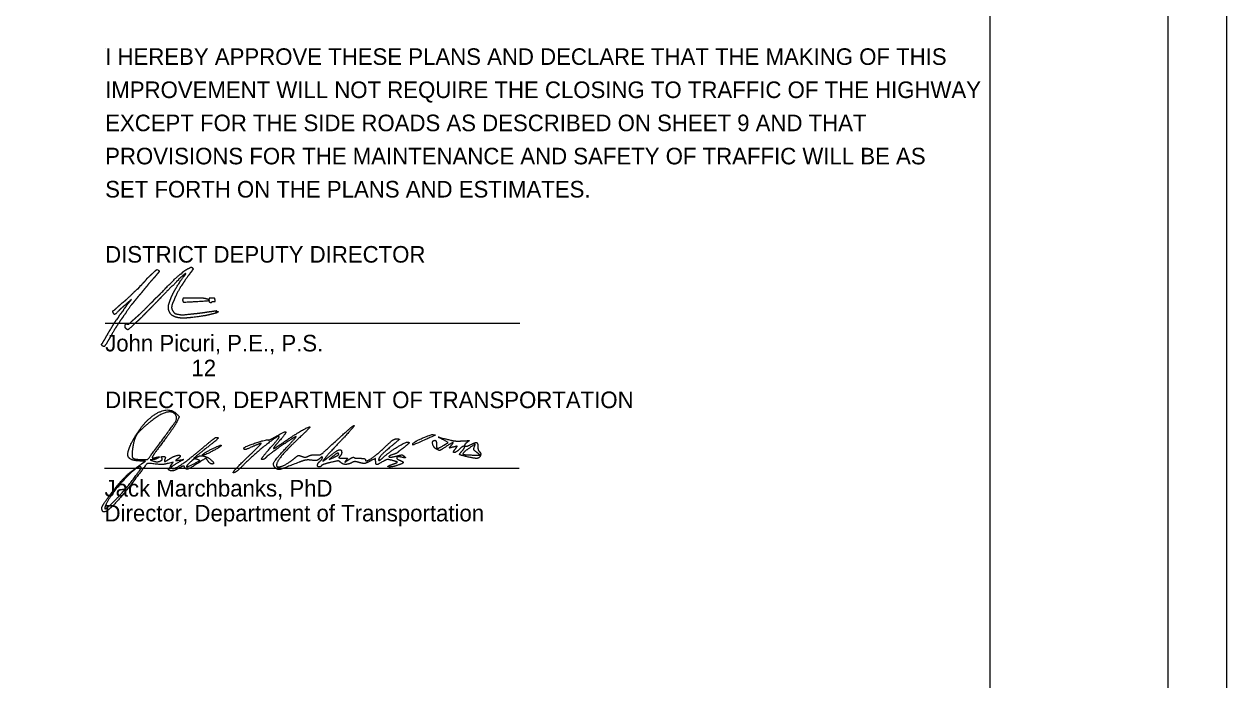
# Model space of a CAD drawing. Extents: x -5.4 to 71.3, y -12 to 22.
# Drawn here: x 23.84 to 34, y 5.54 to 11.08 of the extents above; entities that cross this region are included whole.
import ezdxf

# ---------------------------------------------------------------- set-up
doc = ezdxf.new("R2010")
doc.units = 0
for name, color, linetype in [('SH_Border', 7, 'Continuous'), ('SH_Cut_Line', 7, 'Continuous'), ('SH_Data', 7, 'Continuous'), ('SH_Text', 7, 'Continuous')]:
    doc.layers.add(name, color=color, linetype=linetype)

msp = doc.modelspace()

# ---------------------------------------------------------------- linework, layer by layer
at = {"layer": 'SH_Border'}
msp.add_line((32, 0.5), (32, 21.5), dxfattribs=at)
msp.add_lwpolyline([(1.5, 21.5), (33.5, 21.5), (33.5, 0.5), (1.5, 0.5)], close=True, dxfattribs=at)
at = {"layer": 'SH_Cut_Line'}
msp.add_lwpolyline([(0, 0), (34, 0), (34, 22), (0, 22)], close=True, dxfattribs=at)
at = {"layer": 'SH_Data'}
for p, q in [((24.528, 10.875), (24.528, 10.875)), ((24.528, 8.555), (28.028, 8.555)), ((24.523, 7.329), (28.023, 7.329))]:
    msp.add_line(p, q, dxfattribs=at)
at = {"layer": 'SH_Text'}
for p, q in [((25.184, 8.741), (25.184, 8.741)), ((25.407, 8.734), (25.407, 8.734)), ((24.703, 8.509), (24.703, 8.509)), ((24.512, 8.357), (24.512, 8.357)), ((24.986, 7.534), (24.986, 7.534)), ((27.125, 7.533), (27.125, 7.533)), ((25.351, 7.444), (25.351, 7.444)), ((25.723, 7.415), (25.723, 7.415)), ((26.5, 7.446), (26.5, 7.446)), ((27.577, 7.427), (27.577, 7.427)), ((25.306, 7.402), (25.306, 7.402))]:
    msp.add_line(p, q, dxfattribs=at)
for points in [[(24.953, 8.998), (24.964, 9.008), (24.973, 9.003)], [(24.747, 8.75), (24.75, 8.757), (24.744, 8.75)], [(25.277, 8.765), (25.186, 8.765), (25.184, 8.757)], [(25.429, 8.766), (25.407, 8.766), (25.404, 8.752)], [(25.442, 8.736), (25.457, 8.736), (25.456, 8.749)], [(27.389, 7.523), (27.425, 7.545), (27.384, 7.568)], [(26.448, 7.426), (26.419, 7.401), (26.459, 7.42)], [(27.637, 7.44), (27.694, 7.44), (27.665, 7.462)], [(24.838, 7.367), (24.869, 7.388), (24.831, 7.389)], [(25.081, 7.347), (25.102, 7.379), (25.06, 7.369)]]:
    msp.add_lwpolyline(points, dxfattribs=at)
for points in [[(24.88, 8.928), (24.88, 8.929), (24.894, 8.943), (24.911, 8.958)], [(24.911, 8.958), (24.928, 8.974), (24.947, 8.992), (24.953, 8.998)], [(24.956, 8.955), (24.949, 8.946), (24.941, 8.937), (24.938, 8.934)], [(24.976, 8.979), (24.972, 8.975), (24.963, 8.964), (24.956, 8.955)], [(24.973, 9.003), (24.985, 8.996), (24.985, 8.99), (24.976, 8.979)], [(24.999, 8.807), (25.069, 8.881), (25.161, 8.969), (25.17, 8.971)], [(25.119, 8.836), (25.131, 8.858), (25.186, 8.943), (25.193, 8.949)], [(25.21, 8.974), (25.21, 8.976), (25.185, 8.957), (25.162, 8.936)], [(25.17, 8.971), (25.174, 8.972), (25.178, 8.975), (25.178, 8.977)], [(25.178, 8.977), (25.178, 8.982), (25.204, 9.001), (25.23, 9.015)], [(25.193, 8.949), (25.197, 8.953), (25.21, 8.971), (25.21, 8.974)], [(25.238, 8.964), (25.23, 8.955), (25.227, 8.951), (25.2, 8.912)], [(25.23, 9.015), (25.253, 9.027), (25.258, 9.028), (25.268, 9.016)], [(25.242, 8.972), (25.242, 8.97), (25.24, 8.967), (25.238, 8.964)], [(25.252, 8.984), (25.246, 8.979), (25.242, 8.973), (25.242, 8.972)], [(25.261, 8.997), (25.261, 8.996), (25.257, 8.99), (25.252, 8.984)], [(25.267, 9.005), (25.264, 9.002), (25.261, 8.998), (25.261, 8.997)], [(25.268, 9.016), (25.271, 9.012), (25.271, 9.01), (25.267, 9.005)], [(24.771, 8.815), (24.787, 8.831), (24.804, 8.845), (24.807, 8.846)], [(24.807, 8.846), (24.811, 8.847), (24.813, 8.849), (24.812, 8.85)], [(24.812, 8.85), (24.811, 8.851), (24.814, 8.855), (24.818, 8.859)], [(24.818, 8.859), (24.822, 8.863), (24.825, 8.867), (24.824, 8.868)], [(24.824, 8.868), (24.823, 8.869), (24.825, 8.871), (24.829, 8.872)], [(24.829, 8.872), (24.833, 8.873), (24.836, 8.875), (24.836, 8.876)], [(24.836, 8.876), (24.836, 8.878), (24.846, 8.889), (24.858, 8.902)], [(24.863, 8.846), (24.857, 8.839), (24.846, 8.825), (24.837, 8.814)], [(24.858, 8.902), (24.87, 8.915), (24.88, 8.927), (24.88, 8.928)], [(24.885, 8.873), (24.879, 8.865), (24.869, 8.853), (24.863, 8.846)], [(24.938, 8.934), (24.927, 8.922), (24.896, 8.887), (24.885, 8.873)], [(25.094, 8.867), (25.092, 8.867), (25.062, 8.836), (24.992, 8.763)], [(25.13, 8.906), (25.13, 8.903), (25.097, 8.867), (25.094, 8.867)], [(25.172, 8.87), (25.165, 8.864), (25.125, 8.788), (25.112, 8.757)], [(25.133, 8.909), (25.132, 8.909), (25.13, 8.908), (25.13, 8.906)], [(25.146, 8.92), (25.146, 8.917), (25.138, 8.909), (25.133, 8.909)], [(25.162, 8.936), (25.153, 8.929), (25.146, 8.922), (25.146, 8.92)], [(25.2, 8.912), (25.186, 8.89), (25.173, 8.871), (25.172, 8.87)], [(24.678, 8.729), (24.696, 8.743), (24.73, 8.774), (24.771, 8.815)], [(24.744, 8.75), (24.732, 8.738), (24.709, 8.718), (24.685, 8.697)], [(24.734, 8.734), (24.739, 8.739), (24.745, 8.747), (24.747, 8.75)], [(24.788, 8.755), (24.787, 8.754), (24.779, 8.744), (24.771, 8.734)], [(24.802, 8.773), (24.795, 8.764), (24.788, 8.756), (24.788, 8.755)], [(24.818, 8.792), (24.816, 8.79), (24.809, 8.781), (24.802, 8.773)], [(24.837, 8.814), (24.829, 8.804), (24.82, 8.794), (24.818, 8.792)], [(24.992, 8.763), (24.967, 8.737), (24.931, 8.7), (24.912, 8.681)], [(24.926, 8.734), (24.933, 8.739), (24.938, 8.745), (24.938, 8.747)], [(24.938, 8.747), (24.938, 8.749), (24.947, 8.758), (24.958, 8.768)], [(24.958, 8.768), (24.969, 8.777), (24.987, 8.795), (24.999, 8.807)], [(25.066, 8.714), (25.067, 8.718), (25.071, 8.729), (25.074, 8.739)], [(25.074, 8.739), (25.079, 8.755), (25.097, 8.798), (25.104, 8.809)], [(25.104, 8.737), (25.091, 8.71), (25.088, 8.674), (25.097, 8.66)], [(25.104, 8.809), (25.106, 8.812), (25.112, 8.824), (25.119, 8.836)], [(25.112, 8.757), (25.11, 8.75), (25.106, 8.741), (25.104, 8.737)], [(25.184, 8.757), (25.182, 8.753), (25.182, 8.746), (25.184, 8.741)], [(25.184, 8.741), (25.188, 8.731), (25.191, 8.731), (25.284, 8.736)], [(25.371, 8.762), (25.369, 8.763), (25.327, 8.765), (25.277, 8.765)], [(25.284, 8.736), (25.385, 8.741), (25.422, 8.749), (25.388, 8.757)], [(25.388, 8.757), (25.381, 8.758), (25.373, 8.761), (25.371, 8.762)], [(25.404, 8.752), (25.402, 8.741), (25.402, 8.738), (25.407, 8.734)], [(25.428, 8.733), (25.428, 8.734), (25.434, 8.736), (25.442, 8.736)], [(25.452, 8.764), (25.451, 8.764), (25.441, 8.765), (25.429, 8.766)], [(25.456, 8.749), (25.455, 8.756), (25.453, 8.763), (25.452, 8.764)], [(24.597, 8.64), (24.591, 8.652), (24.591, 8.658), (24.598, 8.66)], [(24.643, 8.659), (24.612, 8.628), (24.605, 8.625), (24.597, 8.64)], [(24.598, 8.66), (24.601, 8.661), (24.614, 8.671), (24.625, 8.682)], [(24.625, 8.682), (24.646, 8.702), (24.652, 8.707), (24.678, 8.729)], [(24.685, 8.697), (24.672, 8.686), (24.653, 8.669), (24.643, 8.659)], [(24.645, 8.61), (24.649, 8.619), (24.656, 8.629), (24.661, 8.634)], [(24.661, 8.634), (24.665, 8.639), (24.669, 8.645), (24.67, 8.647)], [(24.67, 8.647), (24.671, 8.65), (24.674, 8.653), (24.676, 8.653)], [(24.676, 8.653), (24.677, 8.653), (24.679, 8.655), (24.679, 8.657)], [(24.679, 8.657), (24.679, 8.66), (24.68, 8.662), (24.682, 8.662)], [(24.682, 8.662), (24.684, 8.662), (24.685, 8.664), (24.685, 8.667)], [(24.685, 8.667), (24.685, 8.669), (24.687, 8.673), (24.689, 8.676)], [(24.704, 8.644), (24.704, 8.642), (24.701, 8.637), (24.686, 8.619)], [(24.689, 8.676), (24.701, 8.688), (24.711, 8.704), (24.709, 8.707)], [(24.751, 8.71), (24.745, 8.703), (24.704, 8.646), (24.704, 8.644)], [(24.709, 8.707), (24.708, 8.71), (24.708, 8.71), (24.71, 8.709)], [(24.71, 8.709), (24.712, 8.708), (24.716, 8.711), (24.719, 8.716)], [(24.719, 8.716), (24.722, 8.721), (24.729, 8.729), (24.734, 8.734)], [(24.771, 8.734), (24.762, 8.723), (24.754, 8.712), (24.751, 8.71)], [(24.812, 8.622), (24.825, 8.633), (24.871, 8.679), (24.897, 8.706)], [(24.912, 8.681), (24.894, 8.663), (24.866, 8.634), (24.849, 8.617)], [(24.897, 8.706), (24.907, 8.716), (24.92, 8.729), (24.926, 8.734)], [(25.068, 8.655), (25.062, 8.667), (25.061, 8.703), (25.066, 8.714)], [(25.13, 8.603), (25.104, 8.611), (25.077, 8.633), (25.068, 8.655)], [(25.097, 8.66), (25.11, 8.64), (25.123, 8.632), (25.156, 8.627)], [(25.244, 8.63), (25.3, 8.636), (25.35, 8.642), (25.381, 8.647)], [(25.381, 8.647), (25.394, 8.649), (25.424, 8.653), (25.434, 8.654)], [(25.407, 8.734), (25.414, 8.729), (25.428, 8.728), (25.428, 8.733)], [(25.459, 8.637), (25.455, 8.636), (25.441, 8.633), (25.428, 8.63)], [(25.434, 8.654), (25.438, 8.655), (25.442, 8.656), (25.442, 8.656)], [(25.442, 8.656), (25.442, 8.656), (25.449, 8.657), (25.458, 8.657)], [(25.458, 8.657), (25.47, 8.658), (25.472, 8.658), (25.466, 8.656)], [(25.466, 8.656), (25.459, 8.653), (25.459, 8.653), (25.47, 8.653)], [(25.47, 8.641), (25.468, 8.639), (25.462, 8.637), (25.459, 8.637)], [(25.47, 8.653), (25.477, 8.653), (25.482, 8.651), (25.482, 8.649)], [(25.479, 8.646), (25.477, 8.646), (25.473, 8.644), (25.47, 8.641)], [(25.482, 8.649), (25.482, 8.648), (25.481, 8.646), (25.479, 8.646)], [(24.576, 8.506), (24.593, 8.534), (24.601, 8.547), (24.608, 8.558)], [(24.608, 8.558), (24.613, 8.565), (24.618, 8.574), (24.621, 8.578)], [(24.644, 8.557), (24.63, 8.535), (24.617, 8.515), (24.615, 8.513)], [(24.621, 8.578), (24.623, 8.582), (24.626, 8.585), (24.628, 8.585)], [(24.628, 8.585), (24.63, 8.585), (24.631, 8.588), (24.631, 8.59)], [(24.631, 8.59), (24.631, 8.593), (24.632, 8.595), (24.634, 8.595)], [(24.634, 8.595), (24.635, 8.595), (24.64, 8.602), (24.645, 8.61)], [(24.673, 8.598), (24.671, 8.597), (24.659, 8.579), (24.644, 8.557)], [(24.679, 8.608), (24.677, 8.603), (24.674, 8.599), (24.673, 8.598)], [(24.686, 8.619), (24.684, 8.617), (24.681, 8.612), (24.679, 8.608)], [(24.698, 8.528), (24.698, 8.546), (24.7, 8.548), (24.714, 8.546)], [(24.777, 8.549), (24.729, 8.503), (24.715, 8.495), (24.703, 8.509)], [(24.714, 8.546), (24.724, 8.544), (24.727, 8.545), (24.744, 8.562)], [(24.744, 8.562), (24.755, 8.572), (24.772, 8.587), (24.783, 8.596)], [(24.81, 8.579), (24.805, 8.574), (24.79, 8.561), (24.777, 8.549)], [(24.783, 8.596), (24.793, 8.605), (24.806, 8.617), (24.812, 8.622)], [(24.849, 8.617), (24.833, 8.6), (24.815, 8.583), (24.81, 8.579)], [(25.256, 8.601), (25.216, 8.596), (25.15, 8.597), (25.13, 8.603)], [(25.156, 8.627), (25.177, 8.623), (25.188, 8.624), (25.244, 8.63)], [(25.428, 8.63), (25.39, 8.62), (25.351, 8.613), (25.256, 8.601)], [(24.511, 8.395), (24.519, 8.407), (24.53, 8.426), (24.536, 8.437)], [(24.536, 8.437), (24.541, 8.447), (24.547, 8.456), (24.548, 8.457)], [(24.548, 8.457), (24.55, 8.457), (24.551, 8.46), (24.551, 8.462)], [(24.551, 8.462), (24.551, 8.464), (24.556, 8.473), (24.561, 8.482)], [(24.561, 8.482), (24.567, 8.491), (24.574, 8.501), (24.576, 8.506)], [(24.571, 8.437), (24.567, 8.431), (24.564, 8.425), (24.564, 8.424)], [(24.587, 8.465), (24.582, 8.456), (24.575, 8.444), (24.571, 8.437)], [(24.615, 8.513), (24.613, 8.51), (24.608, 8.503), (24.587, 8.465)], [(24.703, 8.509), (24.699, 8.513), (24.697, 8.519), (24.698, 8.528)], [(24.502, 8.366), (24.497, 8.373), (24.498, 8.375), (24.511, 8.395)], [(24.512, 8.357), (24.509, 8.358), (24.504, 8.362), (24.502, 8.366)], [(24.519, 8.355), (24.518, 8.356), (24.515, 8.356), (24.512, 8.357)], [(24.544, 8.392), (24.544, 8.388), (24.521, 8.355), (24.519, 8.355)], [(24.554, 8.408), (24.549, 8.4), (24.544, 8.393), (24.544, 8.392)], [(24.564, 8.424), (24.564, 8.423), (24.559, 8.416), (24.554, 8.408)], [(24.774, 7.585), (24.861, 7.735), (25.069, 7.851), (25.134, 7.785)], [(25.125, 7.776), (25.099, 7.818), (24.973, 7.777), (24.878, 7.695)], [(24.986, 7.534), (25.107, 7.697), (25.139, 7.753), (25.125, 7.776)], [(25.135, 7.723), (25.124, 7.7), (25.072, 7.624), (25.02, 7.555)], [(25.134, 7.785), (25.153, 7.766), (25.153, 7.761), (25.135, 7.723)], [(24.878, 7.695), (24.811, 7.638), (24.772, 7.574), (24.761, 7.503)], [(25.969, 7.596), (26.048, 7.643), (26.06, 7.629), (26.001, 7.562)], [(26.028, 7.543), (26.109, 7.6), (26.24, 7.677), (26.256, 7.677)], [(26.256, 7.677), (26.26, 7.677), (26.219, 7.634), (26.164, 7.582)], [(26.482, 7.563), (26.557, 7.632), (26.623, 7.689), (26.629, 7.689)], [(26.629, 7.689), (26.635, 7.689), (26.583, 7.629), (26.513, 7.555)], [(24.831, 7.389), (24.733, 7.39), (24.709, 7.471), (24.774, 7.585)], [(24.839, 7.402), (24.886, 7.402), (24.891, 7.406), (24.986, 7.534)], [(25.02, 7.555), (24.968, 7.486), (24.925, 7.425), (24.925, 7.42)], [(25.351, 7.444), (25.371, 7.462), (25.503, 7.528), (25.508, 7.522)], [(25.508, 7.522), (25.515, 7.516), (25.372, 7.439), (25.354, 7.439)], [(25.364, 7.511), (25.415, 7.554), (25.46, 7.589), (25.465, 7.589)], [(25.465, 7.589), (25.49, 7.59), (25.467, 7.564), (25.381, 7.497)], [(25.997, 7.596), (25.987, 7.606), (25.778, 7.439), (25.7, 7.36)], [(25.7, 7.499), (25.7, 7.509), (25.888, 7.572), (25.903, 7.567)], [(25.723, 7.415), (25.794, 7.483), (25.849, 7.539), (25.846, 7.539)], [(25.846, 7.539), (25.842, 7.539), (25.813, 7.528), (25.781, 7.514)], [(26.137, 7.596), (26.088, 7.568), (25.9, 7.436), (25.887, 7.42)], [(25.903, 7.567), (25.909, 7.565), (25.938, 7.579), (25.969, 7.596)], [(25.919, 7.496), (25.966, 7.548), (26.001, 7.593), (25.997, 7.596)], [(25.965, 7.331), (25.94, 7.356), (25.969, 7.407), (26.072, 7.517)], [(26.001, 7.562), (25.973, 7.53), (25.95, 7.501), (25.95, 7.496)], [(25.95, 7.496), (25.95, 7.492), (25.985, 7.513), (26.028, 7.543)], [(26.164, 7.582), (26.064, 7.488), (25.975, 7.38), (25.975, 7.353)], [(26.072, 7.517), (26.118, 7.566), (26.148, 7.602), (26.137, 7.596)], [(26.307, 7.441), (26.341, 7.438), (26.364, 7.455), (26.482, 7.563)], [(26.513, 7.555), (26.384, 7.418), (26.352, 7.371), (26.434, 7.438)], [(26.962, 7.529), (26.888, 7.468), (26.837, 7.415), (26.837, 7.398)], [(26.872, 7.416), (26.925, 7.465), (27.072, 7.555), (27.089, 7.549)], [(26.89, 7.507), (26.936, 7.551), (26.973, 7.577), (26.99, 7.576)], [(26.99, 7.576), (27.015, 7.576), (27.011, 7.569), (26.962, 7.529)], [(27.089, 7.549), (27.098, 7.546), (27.082, 7.528), (27.055, 7.507)], [(27.125, 7.533), (27.125, 7.545), (27.278, 7.616), (27.297, 7.612)], [(27.196, 7.554), (27.134, 7.526), (27.125, 7.523), (27.125, 7.533)], [(27.297, 7.612), (27.317, 7.608), (27.318, 7.608), (27.196, 7.554)], [(27.326, 7.489), (27.299, 7.503), (27.288, 7.564), (27.312, 7.564)], [(27.312, 7.564), (27.319, 7.564), (27.325, 7.55), (27.325, 7.533)], [(27.325, 7.533), (27.325, 7.496), (27.339, 7.494), (27.389, 7.523)], [(27.384, 7.568), (27.341, 7.592), (27.341, 7.592), (27.444, 7.566)], [(27.448, 7.518), (27.473, 7.548), (27.457, 7.544), (27.401, 7.507)], [(27.468, 7.507), (27.435, 7.499), (27.433, 7.5), (27.448, 7.518)], [(27.444, 7.566), (27.464, 7.56), (27.509, 7.557), (27.544, 7.559)], [(27.544, 7.559), (27.598, 7.562), (27.603, 7.561), (27.583, 7.546)], [(27.583, 7.546), (27.555, 7.525), (27.578, 7.508), (27.611, 7.526)], [(27.645, 7.508), (27.655, 7.533), (27.647, 7.53), (27.584, 7.485)], [(27.611, 7.526), (27.652, 7.548), (27.675, 7.542), (27.675, 7.511)], [(24.761, 7.503), (24.75, 7.43), (24.771, 7.402), (24.839, 7.402)], [(24.925, 7.42), (24.925, 7.416), (24.94, 7.415), (24.959, 7.42)], [(24.975, 7.415), (24.965, 7.408), (24.945, 7.402), (24.931, 7.401)], [(24.935, 7.389), (24.965, 7.377), (25.021, 7.401), (25.004, 7.419)], [(24.959, 7.42), (24.985, 7.426), (24.989, 7.424), (24.975, 7.415)], [(25.004, 7.419), (24.999, 7.423), (25.006, 7.427), (25.018, 7.427)], [(25.018, 7.427), (25.032, 7.427), (25.038, 7.42), (25.033, 7.408)], [(25.069, 7.406), (25.098, 7.426), (25.162, 7.444), (25.162, 7.432)], [(25.103, 7.327), (25.126, 7.327), (25.252, 7.416), (25.364, 7.511)], [(25.162, 7.432), (25.162, 7.427), (25.153, 7.416), (25.141, 7.408)], [(25.381, 7.497), (25.288, 7.424), (25.266, 7.402), (25.31, 7.426)], [(25.31, 7.426), (25.323, 7.433), (25.347, 7.435), (25.363, 7.43)], [(25.354, 7.439), (25.35, 7.439), (25.348, 7.441), (25.351, 7.444)], [(25.363, 7.43), (25.4, 7.421), (25.458, 7.364), (25.431, 7.364)], [(25.612, 7.29), (25.602, 7.29), (25.652, 7.346), (25.723, 7.415)], [(25.781, 7.514), (25.719, 7.487), (25.7, 7.484), (25.7, 7.499)], [(25.853, 7.402), (25.843, 7.402), (25.872, 7.443), (25.919, 7.496)], [(25.887, 7.42), (25.879, 7.41), (25.864, 7.402), (25.853, 7.402)], [(25.993, 7.339), (26.015, 7.339), (26.096, 7.385), (26.132, 7.417)], [(26.132, 7.417), (26.153, 7.435), (26.166, 7.437), (26.189, 7.428)], [(26.189, 7.428), (26.209, 7.421), (26.228, 7.422), (26.244, 7.431)], [(26.244, 7.431), (26.258, 7.438), (26.286, 7.443), (26.307, 7.441)], [(26.362, 7.418), (26.362, 7.425), (26.352, 7.422), (26.34, 7.41)], [(26.344, 7.389), (26.354, 7.398), (26.362, 7.411), (26.362, 7.418)], [(26.434, 7.438), (26.482, 7.478), (26.525, 7.489), (26.525, 7.461)], [(26.5, 7.446), (26.5, 7.459), (26.476, 7.45), (26.448, 7.426)], [(26.459, 7.42), (26.482, 7.431), (26.5, 7.443), (26.5, 7.446)], [(26.51, 7.429), (26.498, 7.418), (26.504, 7.414), (26.536, 7.414)], [(26.525, 7.461), (26.525, 7.452), (26.518, 7.438), (26.51, 7.429)], [(26.583, 7.399), (26.604, 7.414), (26.625, 7.423), (26.629, 7.419)], [(26.629, 7.419), (26.632, 7.415), (26.656, 7.412), (26.68, 7.412)], [(26.725, 7.4), (26.725, 7.377), (26.82, 7.439), (26.89, 7.507)], [(26.837, 7.398), (26.837, 7.391), (26.853, 7.399), (26.872, 7.416)], [(26.965, 7.446), (26.916, 7.431), (26.935, 7.417), (26.987, 7.431)], [(27, 7.463), (26.996, 7.459), (26.981, 7.451), (26.965, 7.446)], [(26.987, 7.431), (27.026, 7.441), (27.041, 7.441), (27.053, 7.428)], [(27.034, 7.421), (26.998, 7.43), (26.984, 7.407), (27.019, 7.394)], [(27.055, 7.507), (27.028, 7.487), (27.003, 7.467), (27, 7.463)], [(27.053, 7.428), (27.066, 7.416), (27.062, 7.414), (27.034, 7.421)], [(27.401, 7.507), (27.361, 7.481), (27.347, 7.477), (27.326, 7.489)], [(27.488, 7.496), (27.502, 7.514), (27.5, 7.515), (27.468, 7.507)], [(27.516, 7.487), (27.485, 7.457), (27.461, 7.464), (27.488, 7.496)], [(27.542, 7.475), (27.572, 7.508), (27.55, 7.519), (27.516, 7.487)], [(27.577, 7.427), (27.523, 7.44), (27.517, 7.447), (27.542, 7.475)], [(27.584, 7.485), (27.542, 7.454), (27.558, 7.44), (27.637, 7.44)], [(27.696, 7.434), (27.688, 7.413), (27.646, 7.41), (27.577, 7.427)], [(27.665, 7.462), (27.644, 7.478), (27.639, 7.491), (27.645, 7.508)], [(27.675, 7.511), (27.675, 7.495), (27.681, 7.475), (27.689, 7.468)], [(27.689, 7.468), (27.697, 7.46), (27.7, 7.445), (27.696, 7.434)], [(24.831, 7.338), (24.81, 7.358), (24.591, 7.133), (24.545, 7.042)], [(24.587, 7.125), (24.665, 7.225), (24.745, 7.302), (24.838, 7.367)], [(24.615, 7.061), (24.683, 7.13), (24.838, 7.33), (24.831, 7.338)], [(24.919, 7.367), (24.886, 7.37), (24.874, 7.36), (24.797, 7.258)], [(24.931, 7.401), (24.909, 7.4), (24.909, 7.399), (24.935, 7.389)], [(25.06, 7.369), (25.02, 7.359), (24.998, 7.359), (24.919, 7.367)], [(25.033, 7.408), (25.024, 7.385), (25.037, 7.384), (25.069, 7.406)], [(25.08, 7.307), (25.061, 7.314), (25.062, 7.318), (25.081, 7.347)], [(25.146, 7.327), (25.121, 7.312), (25.091, 7.303), (25.08, 7.307)], [(25.148, 7.378), (25.096, 7.349), (25.077, 7.327), (25.103, 7.327)], [(25.141, 7.408), (25.122, 7.394), (25.124, 7.392), (25.156, 7.397)], [(25.197, 7.341), (25.195, 7.349), (25.175, 7.344), (25.146, 7.327)], [(25.156, 7.397), (25.193, 7.403), (25.193, 7.403), (25.148, 7.378)], [(25.312, 7.37), (25.243, 7.326), (25.206, 7.316), (25.197, 7.341)], [(25.253, 7.386), (25.209, 7.345), (25.22, 7.336), (25.278, 7.366)], [(25.306, 7.402), (25.289, 7.409), (25.272, 7.403), (25.253, 7.386)], [(25.278, 7.366), (25.324, 7.39), (25.328, 7.394), (25.306, 7.402)], [(25.397, 7.389), (25.38, 7.413), (25.378, 7.413), (25.312, 7.37)], [(25.431, 7.364), (25.422, 7.364), (25.406, 7.375), (25.397, 7.389)], [(25.7, 7.36), (25.662, 7.321), (25.623, 7.29), (25.612, 7.29)], [(26.165, 7.379), (26.019, 7.321), (25.984, 7.313), (25.965, 7.331)], [(25.975, 7.353), (25.975, 7.346), (25.983, 7.339), (25.993, 7.339)], [(26.27, 7.396), (26.241, 7.4), (26.201, 7.393), (26.165, 7.379)], [(26.34, 7.41), (26.324, 7.396), (26.303, 7.392), (26.27, 7.396)], [(26.337, 7.339), (26.318, 7.339), (26.323, 7.372), (26.344, 7.389)], [(26.355, 7.35), (26.351, 7.344), (26.343, 7.339), (26.337, 7.339)], [(26.431, 7.377), (26.393, 7.368), (26.358, 7.355), (26.355, 7.35)], [(26.515, 7.379), (26.504, 7.39), (26.484, 7.39), (26.431, 7.377)], [(26.612, 7.376), (26.581, 7.36), (26.533, 7.361), (26.515, 7.379)], [(26.536, 7.414), (26.574, 7.414), (26.576, 7.412), (26.561, 7.393)], [(26.561, 7.393), (26.549, 7.378), (26.555, 7.38), (26.583, 7.399)], [(26.676, 7.376), (26.649, 7.384), (26.626, 7.384), (26.612, 7.376)], [(26.765, 7.388), (26.728, 7.369), (26.709, 7.367), (26.676, 7.376)], [(26.68, 7.412), (26.705, 7.412), (26.725, 7.407), (26.725, 7.4)], [(26.812, 7.388), (26.812, 7.411), (26.811, 7.411), (26.765, 7.388)], [(26.874, 7.385), (26.829, 7.358), (26.812, 7.359), (26.812, 7.388)], [(26.957, 7.393), (26.919, 7.403), (26.902, 7.401), (26.874, 7.385)], [(26.993, 7.352), (26.947, 7.336), (26.9, 7.342), (26.944, 7.358)], [(26.944, 7.358), (26.957, 7.363), (26.977, 7.37), (26.987, 7.374)], [(26.987, 7.374), (26.999, 7.378), (26.987, 7.385), (26.957, 7.393)], [(27.019, 7.394), (27.049, 7.382), (27.04, 7.367), (26.993, 7.352)], [(24.797, 7.258), (24.645, 7.056), (24.5, 6.927), (24.5, 6.994)], [(24.5, 6.994), (24.5, 7.004), (24.539, 7.063), (24.587, 7.125)], [(24.545, 7.042), (24.514, 6.981), (24.545, 6.99), (24.615, 7.061)]]:
    msp.add_open_spline(points, degree=2, dxfattribs=at)

# ---------------------------------------------------------------- texts
at = {"layer": 'SH_Data'}
for s, p in [('I HEREBY APPROVE THESE PLANS AND DECLARE THAT THE MAKING OF THIS', (24.528, 10.735)), ('IMPROVEMENT WILL NOT REQUIRE THE CLOSING TO TRAFFIC OF THE HIGHWAY', (24.528, 10.455)), ('EXCEPT FOR THE SIDE ROADS AS DESCRIBED ON SHEET 9 AND THAT', (24.528, 10.175)), ('PROVISIONS FOR THE MAINTENANCE AND SAFETY OF TRAFFIC WILL BE AS', (24.528, 9.895)), ('SET FORTH ON THE PLANS AND ESTIMATES.', (24.528, 9.615))]:
    msp.add_text(s, height=0.14, dxfattribs=at).set_placement(p)
at = {"layer": 'SH_Text'}
for s, p in [('DISTRICT DEPUTY DIRECTOR', (24.528, 9.065)), ('John Picuri, P.E., P.S.', (24.528, 8.315)), ('              12', (24.528, 8.105)), ('DIRECTOR, DEPARTMENT OF TRANSPORTATION', (24.528, 7.836)), ('Jack Marchbanks, PhD', (24.523, 7.089)), ('Director, Department of Transportation', (24.523, 6.879))]:
    msp.add_text(s, height=0.14, dxfattribs=at).set_placement(p)

doc.saveas('drawing.dxf')
